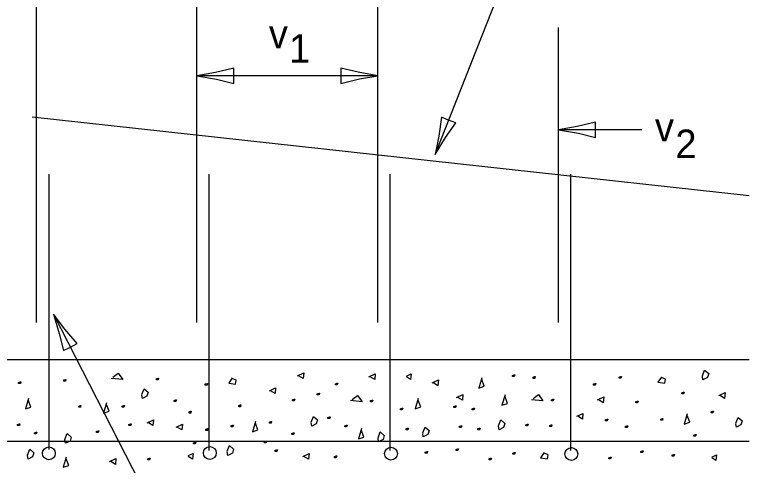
# Model space of a CAD drawing. Extents: x 2133490 to 2172050, y 2138301 to 2145980.
# Drawn here: x 2139073.9 to 2139254.8, y 2141727.2 to 2141838.2 of the extents above; entities that cross this region are included whole.
import ezdxf

# ---------------------------------------------------------------- set-up
doc = ezdxf.new("R2010")
doc.units = 0
for name, color, linetype in [('Level 40', 7, 'Continuous'), ('Level 63', 7, 'Continuous'), ('ROW_EX_Private Boundary Items', 7, 'Continuous'), ('ROW_PR_Notes', 7, 'Continuous'), ('Topo_Bridge Structures', 7, 'Continuous')]:
    doc.layers.add(name, color=color, linetype=linetype)

msp = doc.modelspace()

# ---------------------------------------------------------------- linework, layer by layer
at = {"layer": 'Level 40'}
msp.add_line((2138878.97, 2141753.19), (2139254.81, 2141753.19), dxfattribs=at)
at = {"layer": 'ROW_EX_Private Boundary Items'}
for centre in [(2139082.36, 2141730.13), (2139121.98, 2141730.21), (2139166.58, 2141730.04), (2139211.01, 2141729.95)]:
    msp.add_circle(centre, 1.58, dxfattribs=at)
at = {"layer": 'ROW_PR_Notes'}
for p, q in [((2139177.43, 2141803.74), (2139216.4, 2141902.1)), ((2139079.35, 2141762.3), (2139079.35, 2141885.77)), ((2139118.82, 2141762.3), (2139118.82, 2141865.85)), ((2139163.35, 2141762.3), (2139163.35, 2141865.85)), ((2139207.87, 2141762.3), (2139207.87, 2141835.01)), ((2139163.35, 2141823.12), (2139118.82, 2141823.12)), ((2139254.81, 2141793.52), (2139078.24, 2141812.95)), ((2139228.35, 2141809.82), (2139207.87, 2141809.82)), ((2139082.39, 2141731.04), (2139082.39, 2141798.85)), ((2139121.85, 2141730.81), (2139121.85, 2141798.85)), ((2139166.38, 2141730.81), (2139166.38, 2141798.85)), ((2139210.91, 2141730.81), (2139210.91, 2141798.85)), ((2139083.51, 2141764.38), (2139119.78, 2141693.56)), ((2138855.7, 2141733.07), (2139254.81, 2141733.07))]:
    msp.add_line(p, q, dxfattribs=at)
for points in [[(2139243.26, 2141749.22), (2139243.82, 2141750.63), (2139244.81, 2141749.79), (2139244.53, 2141748.8), (2139243.4, 2141748.24), (2139243.26, 2141749.08)], [(2139098.14, 2141748.85), (2139099.41, 2141749.83), (2139100.53, 2141748.28), (2139097.72, 2141748.57)], [(2139143.57, 2141749.24), (2139145.12, 2141749.95), (2139144.98, 2141748.54), (2139143.85, 2141749.24)], [(2139161.17, 2141748.97), (2139162.72, 2141749.67), (2139162.58, 2141748.27), (2139161.45, 2141748.97)], [(2139170.37, 2141749.16), (2139171.56, 2141749.7), (2139171.42, 2141748.29), (2139170.37, 2141748.94)], [(2139196.68, 2141749.31), (2139196.96, 2141749.45), (2139196.96, 2141749.03), (2139196.82, 2141749.03), (2139196.54, 2141749.03), (2139196.54, 2141749.03), (2139196.54, 2141749.31), (2139196.96, 2141749.45), (2139197.1, 2141749.45), (2139196.96, 2141749.03), (2139196.82, 2141749.03), (2139196.82, 2141749.45)], [(2139201.7, 2141748.85), (2139201.98, 2141749), (2139201.98, 2141748.57), (2139201.84, 2141748.57), (2139201.56, 2141748.57), (2139201.56, 2141748.57), (2139201.56, 2141748.85), (2139201.98, 2141749), (2139202.13, 2141749), (2139201.98, 2141748.57), (2139201.84, 2141748.57), (2139201.84, 2141749)], [(2139222.9, 2141748.91), (2139223.18, 2141749.05), (2139223.18, 2141748.63), (2139223.04, 2141748.63), (2139222.76, 2141748.63), (2139222.76, 2141748.63), (2139222.76, 2141748.91), (2139223.18, 2141749.05), (2139223.32, 2141749.05), (2139223.18, 2141748.63), (2139223.04, 2141748.63), (2139223.04, 2141749.05)], [(2139233.17, 2141748.91), (2139232.32, 2141747.65), (2139234.01, 2141747.37), (2139234.15, 2141748.35), (2139233.17, 2141748.77)], [(2139075.06, 2141747.58), (2139075.34, 2141747.71), (2139075.34, 2141747.29), (2139075.2, 2141747.29), (2139074.92, 2141747.29), (2139074.92, 2141747.29), (2139074.92, 2141747.58), (2139075.34, 2141747.71), (2139075.48, 2141747.71), (2139075.34, 2141747.29), (2139075.2, 2141747.29), (2139075.2, 2141747.71)], [(2139086.15, 2141748.19), (2139086.43, 2141748.33), (2139086.43, 2141747.91), (2139086.29, 2141747.91), (2139086.01, 2141747.91), (2139086.01, 2141747.91), (2139086.01, 2141748.19), (2139086.43, 2141748.33), (2139086.57, 2141748.33), (2139086.43, 2141747.91), (2139086.29, 2141747.91), (2139086.29, 2141748.33)], [(2139108.96, 2141748.52), (2139109.25, 2141748.66), (2139109.25, 2141748.23), (2139109.11, 2141748.23), (2139108.82, 2141748.23), (2139108.82, 2141748.23), (2139108.82, 2141748.52), (2139109.25, 2141748.66), (2139109.39, 2141748.66), (2139109.25, 2141748.23), (2139109.11, 2141748.23), (2139109.11, 2141748.66)], [(2139121.02, 2141747.21), (2139121.3, 2141747.35), (2139121.3, 2141746.93), (2139121.17, 2141746.93), (2139120.88, 2141746.93), (2139120.88, 2141746.93), (2139120.88, 2141747.21), (2139121.3, 2141747.35), (2139121.45, 2141747.35), (2139121.3, 2141746.93), (2139121.17, 2141746.93), (2139121.17, 2141747.35)], [(2139127.5, 2141748.7), (2139126.65, 2141747.43), (2139128.34, 2141747.15), (2139128.48, 2141748.14), (2139127.5, 2141748.56)], [(2139153.08, 2141747.23), (2139153.36, 2141747.37), (2139153.36, 2141746.95), (2139153.22, 2141746.95), (2139152.94, 2141746.95), (2139152.94, 2141746.95), (2139152.94, 2141747.23), (2139153.36, 2141747.37), (2139153.5, 2141747.37), (2139153.36, 2141746.95), (2139153.22, 2141746.95), (2139153.22, 2141747.37)], [(2139176.75, 2141747.48), (2139178.3, 2141748.19), (2139178.15, 2141746.78), (2139177.03, 2141747.48)], [(2139188.94, 2141748.74), (2139188.19, 2141746.2), (2139189.54, 2141746.65), (2139188.94, 2141748.29)], [(2139216.61, 2141747.2), (2139216.89, 2141747.34), (2139216.89, 2141746.91), (2139216.75, 2141746.91), (2139216.47, 2141746.91), (2139216.47, 2141746.91), (2139216.47, 2141747.2), (2139216.89, 2141747.34), (2139217.03, 2141747.34), (2139216.89, 2141746.91), (2139216.75, 2141746.91), (2139216.75, 2141747.34)], [(2139105.23, 2141744.62), (2139105.79, 2141746.03), (2139106.78, 2141745.18), (2139106.5, 2141744.2), (2139105.37, 2141743.64), (2139105.23, 2141744.48)], [(2139136.65, 2141745.53), (2139138.19, 2141746.24), (2139138.05, 2141744.83), (2139136.93, 2141745.53)], [(2139238.34, 2141745.02), (2139238.62, 2141745.16), (2139238.62, 2141744.74), (2139238.48, 2141744.74), (2139238.2, 2141744.74), (2139238.2, 2141744.74), (2139238.2, 2141745.02), (2139238.62, 2141745.16), (2139238.76, 2141745.16), (2139238.62, 2141744.74), (2139238.48, 2141744.74), (2139238.48, 2141745.16)], [(2139077.35, 2141743.6), (2139076.6, 2141741.07), (2139077.94, 2141741.51), (2139077.35, 2141743.16)], [(2139142.46, 2141743.31), (2139142.74, 2141743.46), (2139142.74, 2141743.03), (2139142.6, 2141743.03), (2139142.32, 2141743.03), (2139142.32, 2141743.03), (2139142.32, 2141743.31), (2139142.74, 2141743.46), (2139142.88, 2141743.46), (2139142.74, 2141743.03), (2139142.6, 2141743.03), (2139142.6, 2141743.46)], [(2139148.59, 2141744.8), (2139148.87, 2141744.94), (2139148.87, 2141744.52), (2139148.73, 2141744.52), (2139148.45, 2141744.52), (2139148.45, 2141744.52), (2139148.45, 2141744.8), (2139148.87, 2141744.94), (2139149.01, 2141744.94), (2139148.87, 2141744.52), (2139148.73, 2141744.52), (2139148.73, 2141744.94)], [(2139157.07, 2141743.39), (2139158.33, 2141744.38), (2139159.46, 2141742.83), (2139156.65, 2141743.11)], [(2139173.32, 2141743.65), (2139172.57, 2141741.11), (2139173.92, 2141741.56), (2139173.32, 2141743.2)], [(2139182.76, 2141743.9), (2139184.31, 2141744.6), (2139184.17, 2141743.19), (2139183.05, 2141743.9)], [(2139194.67, 2141744.49), (2139193.92, 2141741.95), (2139195.26, 2141742.4), (2139194.67, 2141744.04)], [(2139201.62, 2141743.61), (2139202.89, 2141744.6), (2139204.01, 2141743.05), (2139201.2, 2141743.33)], [(2139206.26, 2141743.33), (2139206.54, 2141743.47), (2139206.54, 2141743.05), (2139206.4, 2141743.05), (2139206.12, 2141743.05), (2139206.12, 2141743.05), (2139206.12, 2141743.33), (2139206.54, 2141743.47), (2139206.69, 2141743.47), (2139206.54, 2141743.05), (2139206.4, 2141743.05), (2139206.4, 2141743.47)], [(2139217.45, 2141743.3), (2139218.99, 2141744), (2139218.85, 2141742.59), (2139217.73, 2141743.3)], [(2139247.32, 2141744.36), (2139248.86, 2141745.07), (2139248.72, 2141743.66), (2139247.6, 2141744.36)], [(2139089.84, 2141741.73), (2139090.12, 2141741.87), (2139090.12, 2141741.45), (2139089.98, 2141741.45), (2139089.7, 2141741.45), (2139089.7, 2141741.45), (2139089.7, 2141741.73), (2139090.12, 2141741.87), (2139090.26, 2141741.87), (2139090.12, 2141741.45), (2139089.98, 2141741.45), (2139089.98, 2141741.87)], [(2139096.58, 2141742.56), (2139095.83, 2141740.03), (2139097.17, 2141740.47), (2139096.58, 2141742.11)], [(2139100.54, 2141741.73), (2139100.82, 2141741.87), (2139100.82, 2141741.45), (2139100.68, 2141741.45), (2139100.4, 2141741.45), (2139100.4, 2141741.45), (2139100.4, 2141741.73), (2139100.82, 2141741.87), (2139100.96, 2141741.87), (2139100.82, 2141741.45), (2139100.68, 2141741.45), (2139100.68, 2141741.87)], [(2139113.34, 2141743.13), (2139113.62, 2141743.27), (2139113.62, 2141742.85), (2139113.48, 2141742.85), (2139113.2, 2141742.85), (2139113.2, 2141742.85), (2139113.2, 2141743.13), (2139113.62, 2141743.27), (2139113.76, 2141743.27), (2139113.62, 2141742.85), (2139113.48, 2141742.85), (2139113.48, 2141743.27)], [(2139129.24, 2141741.88), (2139129.52, 2141742.02), (2139129.52, 2141741.6), (2139129.38, 2141741.6), (2139129.1, 2141741.6), (2139129.1, 2141741.6), (2139129.1, 2141741.88), (2139129.52, 2141742.02), (2139129.66, 2141742.02), (2139129.52, 2141741.6), (2139129.38, 2141741.6), (2139129.38, 2141742.02)], [(2139161.71, 2141743.11), (2139161.99, 2141743.25), (2139161.99, 2141742.83), (2139161.85, 2141742.83), (2139161.57, 2141742.83), (2139161.57, 2141742.83), (2139161.57, 2141743.11), (2139161.99, 2141743.25), (2139162.13, 2141743.25), (2139161.99, 2141742.83), (2139161.85, 2141742.83), (2139161.85, 2141743.25)], [(2139182.18, 2141741.66), (2139182.47, 2141741.81), (2139182.47, 2141741.38), (2139182.33, 2141741.38), (2139182.04, 2141741.38), (2139182.04, 2141741.38), (2139182.04, 2141741.66), (2139182.47, 2141741.81), (2139182.61, 2141741.81), (2139182.47, 2141741.38), (2139182.33, 2141741.38), (2139182.33, 2141741.81)], [(2139227.02, 2141742.84), (2139227.3, 2141742.98), (2139227.3, 2141742.56), (2139227.16, 2141742.56), (2139226.88, 2141742.56), (2139226.88, 2141742.56), (2139226.88, 2141742.84), (2139227.3, 2141742.98), (2139227.44, 2141742.98), (2139227.3, 2141742.56), (2139227.16, 2141742.56), (2139227.16, 2141742.98)], [(2139117, 2141740.32), (2139117.28, 2141740.46), (2139117.28, 2141740.04), (2139117.14, 2141740.04), (2139116.86, 2141740.04), (2139116.86, 2141740.04), (2139116.86, 2141740.32), (2139117.28, 2141740.46), (2139117.42, 2141740.46), (2139117.28, 2141740.04), (2139117.14, 2141740.04), (2139117.14, 2141740.46)], [(2139169.06, 2141741.08), (2139169.34, 2141741.22), (2139169.34, 2141740.8), (2139169.2, 2141740.8), (2139168.92, 2141740.8), (2139168.92, 2141740.8), (2139168.92, 2141741.08), (2139169.34, 2141741.22), (2139169.48, 2141741.22), (2139169.34, 2141740.8), (2139169.2, 2141740.8), (2139169.2, 2141741.22)], [(2139186.71, 2141741.08), (2139186.99, 2141741.22), (2139186.99, 2141740.8), (2139186.84, 2141740.8), (2139186.57, 2141740.8), (2139186.57, 2141740.8), (2139186.57, 2141741.08), (2139186.99, 2141741.22), (2139187.13, 2141741.22), (2139186.99, 2141740.8), (2139186.84, 2141740.8), (2139186.84, 2141741.22)], [(2139212.31, 2141739.25), (2139213.86, 2141739.95), (2139213.72, 2141738.55), (2139212.59, 2141739.25)], [(2139239.55, 2141739.87), (2139238.81, 2141737.33), (2139240.15, 2141737.78), (2139239.55, 2141739.42)], [(2139245.57, 2141740.33), (2139245.86, 2141740.47), (2139245.86, 2141740.05), (2139245.71, 2141740.05), (2139245.43, 2141740.05), (2139245.43, 2141740.05), (2139245.43, 2141740.33), (2139245.86, 2141740.47), (2139246, 2141740.47), (2139245.86, 2141740.05), (2139245.71, 2141740.05), (2139245.71, 2141740.47)], [(2139106.59, 2141737.65), (2139108.13, 2141738.35), (2139107.99, 2141736.94), (2139106.87, 2141737.65)], [(2139133.21, 2141737.96), (2139132.47, 2141735.43), (2139133.81, 2141735.87), (2139133.21, 2141737.51)], [(2139136.78, 2141737.8), (2139137.06, 2141737.94), (2139137.06, 2141737.52), (2139136.92, 2141737.52), (2139136.64, 2141737.52), (2139136.64, 2141737.52), (2139136.64, 2141737.8), (2139137.06, 2141737.94), (2139137.2, 2141737.94), (2139137.06, 2141737.52), (2139136.92, 2141737.52), (2139136.92, 2141737.94)], [(2139146.93, 2141737.77), (2139147.5, 2141739.18), (2139148.48, 2141738.34), (2139148.2, 2141737.35), (2139147.08, 2141736.79), (2139146.93, 2141737.63)], [(2139151.22, 2141738.97), (2139151.5, 2141739.11), (2139151.5, 2141738.69), (2139151.36, 2141738.69), (2139151.08, 2141738.69), (2139151.08, 2141738.69), (2139151.08, 2141738.97), (2139151.5, 2141739.11), (2139151.64, 2141739.11), (2139151.5, 2141738.69), (2139151.36, 2141738.69), (2139151.36, 2141739.11)], [(2139193.05, 2141736.92), (2139193.61, 2141738.33), (2139194.6, 2141737.48), (2139194.32, 2141736.5), (2139193.19, 2141735.94), (2139193.05, 2141736.78)], [(2139219.55, 2141738.43), (2139219.83, 2141738.57), (2139219.83, 2141738.15), (2139219.69, 2141738.15), (2139219.41, 2141738.15), (2139219.41, 2141738.15), (2139219.41, 2141738.43), (2139219.83, 2141738.57), (2139219.97, 2141738.57), (2139219.83, 2141738.15), (2139219.69, 2141738.15), (2139219.69, 2141738.57)], [(2139233.14, 2141738.55), (2139233.42, 2141738.69), (2139233.42, 2141738.26), (2139233.28, 2141738.26), (2139233, 2141738.26), (2139233, 2141738.26), (2139233, 2141738.55), (2139233.42, 2141738.69), (2139233.56, 2141738.69), (2139233.42, 2141738.26), (2139233.28, 2141738.26), (2139233.28, 2141738.69)], [(2139251.49, 2141737.56), (2139252.06, 2141738.96), (2139253.04, 2141738.12), (2139252.76, 2141737.14), (2139251.64, 2141736.57), (2139251.49, 2141737.42)], [(2139074.8, 2141737.22), (2139075.09, 2141737.36), (2139075.09, 2141736.94), (2139074.94, 2141736.94), (2139074.66, 2141736.94), (2139074.66, 2141736.94), (2139074.66, 2141737.22), (2139075.09, 2141737.36), (2139075.23, 2141737.36), (2139075.09, 2141736.94), (2139074.94, 2141736.94), (2139074.94, 2141737.36)], [(2139102.22, 2141737.22), (2139102.5, 2141737.36), (2139102.5, 2141736.94), (2139102.36, 2141736.94), (2139102.08, 2141736.94), (2139102.08, 2141736.94), (2139102.08, 2141737.22), (2139102.5, 2141737.36), (2139102.64, 2141737.36), (2139102.5, 2141736.94), (2139102.36, 2141736.94), (2139102.36, 2141737.36)], [(2139113.67, 2141736.58), (2139115.22, 2141737.29), (2139115.08, 2141735.88), (2139113.95, 2141736.58)], [(2139121.18, 2141736.05), (2139121.46, 2141736.19), (2139121.46, 2141735.77), (2139121.32, 2141735.77), (2139121.04, 2141735.77), (2139121.04, 2141735.77), (2139121.04, 2141736.05), (2139121.46, 2141736.19), (2139121.6, 2141736.19), (2139121.46, 2141735.77), (2139121.32, 2141735.77), (2139121.32, 2141736.19)], [(2139127.41, 2141736.94), (2139127.69, 2141737.08), (2139127.69, 2141736.66), (2139127.55, 2141736.66), (2139127.27, 2141736.66), (2139127.27, 2141736.66), (2139127.27, 2141736.94), (2139127.69, 2141737.08), (2139127.83, 2141737.08), (2139127.69, 2141736.66), (2139127.55, 2141736.66), (2139127.55, 2141737.08)], [(2139155.38, 2141736.92), (2139155.66, 2141737.06), (2139155.66, 2141736.64), (2139155.52, 2141736.64), (2139155.24, 2141736.64), (2139155.24, 2141736.64), (2139155.24, 2141736.92), (2139155.66, 2141737.06), (2139155.8, 2141737.06), (2139155.66, 2141736.64), (2139155.52, 2141736.64), (2139155.52, 2141737.06)], [(2139159.32, 2141736.21), (2139158.57, 2141733.67), (2139159.91, 2141734.12), (2139159.32, 2141735.76)], [(2139170.47, 2141736.2), (2139170.75, 2141736.34), (2139170.75, 2141735.92), (2139170.61, 2141735.92), (2139170.32, 2141735.92), (2139170.32, 2141735.92), (2139170.32, 2141736.2), (2139170.75, 2141736.34), (2139170.89, 2141736.34), (2139170.75, 2141735.92), (2139170.61, 2141735.92), (2139170.61, 2141736.34)], [(2139174.4, 2141735.17), (2139174.97, 2141736.58), (2139175.96, 2141735.73), (2139175.67, 2141734.75), (2139174.55, 2141734.18), (2139174.4, 2141735.03)], [(2139183.59, 2141736.78), (2139183.87, 2141736.92), (2139183.87, 2141736.5), (2139183.73, 2141736.5), (2139183.45, 2141736.5), (2139183.45, 2141736.5), (2139183.45, 2141736.78), (2139183.87, 2141736.92), (2139184.02, 2141736.92), (2139183.87, 2141736.5), (2139183.73, 2141736.5), (2139183.73, 2141736.92)], [(2139188.11, 2141736.2), (2139188.39, 2141736.34), (2139188.39, 2141735.92), (2139188.25, 2141735.92), (2139187.97, 2141735.92), (2139187.97, 2141735.92), (2139187.97, 2141736.2), (2139188.39, 2141736.34), (2139188.53, 2141736.34), (2139188.39, 2141735.92), (2139188.25, 2141735.92), (2139188.25, 2141736.34)], [(2139199.93, 2141737.14), (2139200.21, 2141737.28), (2139200.21, 2141736.86), (2139200.07, 2141736.86), (2139199.79, 2141736.86), (2139199.79, 2141736.86), (2139199.79, 2141737.14), (2139200.21, 2141737.28), (2139200.35, 2141737.28), (2139200.21, 2141736.86), (2139200.07, 2141736.86), (2139200.07, 2141737.28)], [(2139205.8, 2141736.98), (2139206.08, 2141737.12), (2139206.08, 2141736.7), (2139205.94, 2141736.7), (2139205.66, 2141736.7), (2139205.66, 2141736.7), (2139205.66, 2141736.98), (2139206.08, 2141737.12), (2139206.22, 2141737.12), (2139206.08, 2141736.7), (2139205.94, 2141736.7), (2139205.94, 2141737.12)], [(2139224.46, 2141736.78), (2139224.74, 2141736.92), (2139224.74, 2141736.5), (2139224.6, 2141736.5), (2139224.32, 2141736.5), (2139224.32, 2141736.5), (2139224.32, 2141736.78), (2139224.74, 2141736.92), (2139224.88, 2141736.92), (2139224.74, 2141736.5), (2139224.6, 2141736.5), (2139224.6, 2141736.92)], [(2139078.97, 2141735.17), (2139079.25, 2141735.31), (2139079.25, 2141734.89), (2139079.11, 2141734.89), (2139078.83, 2141734.89), (2139078.83, 2141734.89), (2139078.83, 2141735.17), (2139079.25, 2141735.31), (2139079.39, 2141735.31), (2139079.25, 2141734.89), (2139079.11, 2141734.89), (2139079.11, 2141735.31)], [(2139086.32, 2141733.56), (2139086.89, 2141734.97), (2139087.87, 2141734.13), (2139087.59, 2141733.14), (2139086.46, 2141732.58), (2139086.32, 2141733.42)], [(2139094.2, 2141735.54), (2139094.48, 2141735.68), (2139094.48, 2141735.25), (2139094.34, 2141735.25), (2139094.06, 2141735.25), (2139094.06, 2141735.25), (2139094.06, 2141735.54), (2139094.48, 2141735.68), (2139094.62, 2141735.68), (2139094.48, 2141735.25), (2139094.34, 2141735.25), (2139094.34, 2141735.68)], [(2139142.32, 2141735.03), (2139142.6, 2141735.17), (2139142.6, 2141734.75), (2139142.46, 2141734.75), (2139142.18, 2141734.75), (2139142.18, 2141734.75), (2139142.18, 2141735.03), (2139142.6, 2141735.17), (2139142.74, 2141735.17), (2139142.6, 2141734.75), (2139142.46, 2141734.75), (2139142.46, 2141735.17)], [(2139163.4, 2141733.97), (2139163.96, 2141735.37), (2139164.95, 2141734.53), (2139164.67, 2141733.54), (2139163.54, 2141732.98), (2139163.4, 2141733.82)], [(2139241.3, 2141734.6), (2139241.58, 2141734.75), (2139241.58, 2141734.32), (2139241.44, 2141734.32), (2139241.16, 2141734.32), (2139241.16, 2141734.32), (2139241.16, 2141734.6), (2139241.58, 2141734.75), (2139241.72, 2141734.75), (2139241.58, 2141734.32), (2139241.44, 2141734.32), (2139241.44, 2141734.75)], [(2139118.12, 2141732.72), (2139118.4, 2141732.86), (2139118.4, 2141732.44), (2139118.26, 2141732.44), (2139117.98, 2141732.44), (2139117.98, 2141732.44), (2139117.98, 2141732.72), (2139118.4, 2141732.86), (2139118.55, 2141732.86), (2139118.4, 2141732.44), (2139118.26, 2141732.44), (2139118.26, 2141732.86)], [(2139135.57, 2141733), (2139135.85, 2141733.14), (2139135.85, 2141732.72), (2139135.71, 2141732.72), (2139135.43, 2141732.72), (2139135.43, 2141732.72), (2139135.43, 2141733), (2139135.85, 2141733.14), (2139135.99, 2141733.14), (2139135.85, 2141732.72), (2139135.71, 2141732.72), (2139135.71, 2141733.14)], [(2139077.09, 2141729.69), (2139077.65, 2141731.1), (2139078.63, 2141730.26), (2139078.35, 2141729.27), (2139077.23, 2141728.71), (2139077.09, 2141729.55)], [(2139126.28, 2141730.61), (2139126.85, 2141732.02), (2139127.83, 2141731.17), (2139127.55, 2141730.19), (2139126.43, 2141729.62), (2139126.28, 2141730.47)], [(2139138.21, 2141730.87), (2139138.5, 2141731.01), (2139138.5, 2141730.59), (2139138.36, 2141730.59), (2139138.07, 2141730.59), (2139138.07, 2141730.59), (2139138.07, 2141730.87), (2139138.5, 2141731.01), (2139138.64, 2141731.01), (2139138.5, 2141730.59), (2139138.36, 2141730.59), (2139138.36, 2141731.01)], [(2139182.76, 2141731.09), (2139183.05, 2141731.23), (2139183.05, 2141730.8), (2139182.9, 2141730.8), (2139182.62, 2141730.8), (2139182.62, 2141730.8), (2139182.62, 2141731.09), (2139183.05, 2141731.23), (2139183.19, 2141731.23), (2139183.05, 2141730.8), (2139182.9, 2141730.8), (2139182.9, 2141731.23)], [(2139228.25, 2141730.56), (2139228.53, 2141730.7), (2139228.53, 2141730.28), (2139228.39, 2141730.28), (2139228.11, 2141730.28), (2139228.11, 2141730.28), (2139228.11, 2141730.56), (2139228.53, 2141730.7), (2139228.67, 2141730.7), (2139228.53, 2141730.28), (2139228.39, 2141730.28), (2139228.39, 2141730.7)], [(2139086.65, 2141729.21), (2139085.91, 2141726.67), (2139087.25, 2141727.12), (2139086.65, 2141728.76)], [(2139106.87, 2141728.78), (2139107.15, 2141728.92), (2139107.15, 2141728.5), (2139107.01, 2141728.5), (2139106.72, 2141728.5), (2139106.72, 2141728.5), (2139106.72, 2141728.78), (2139107.15, 2141728.92), (2139107.29, 2141728.92), (2139107.15, 2141728.5), (2139107.01, 2141728.5), (2139107.01, 2141728.92)], [(2139116.67, 2141729.56), (2139117.86, 2141730.1), (2139117.71, 2141728.7), (2139116.67, 2141729.35)], [(2139144.87, 2141729.37), (2139146.42, 2141730.07), (2139146.28, 2141728.66), (2139145.15, 2141729.37)], [(2139152.85, 2141729.32), (2139153.13, 2141729.46), (2139153.13, 2141729.04), (2139152.99, 2141729.04), (2139152.7, 2141729.04), (2139152.7, 2141729.04), (2139152.7, 2141729.32), (2139153.13, 2141729.46), (2139153.27, 2141729.46), (2139153.13, 2141729.04), (2139152.99, 2141729.04), (2139152.99, 2141729.46)], [(2139175.18, 2141730.44), (2139175.46, 2141730.59), (2139175.46, 2141730.16), (2139175.32, 2141730.16), (2139175.03, 2141730.16), (2139175.03, 2141730.16), (2139175.03, 2141730.44), (2139175.46, 2141730.59), (2139175.6, 2141730.59), (2139175.46, 2141730.16), (2139175.32, 2141730.16), (2139175.32, 2141730.59)], [(2139190.89, 2141728.82), (2139191.17, 2141728.96), (2139191.17, 2141728.54), (2139191.03, 2141728.54), (2139190.75, 2141728.54), (2139190.75, 2141728.54), (2139190.75, 2141728.82), (2139191.17, 2141728.96), (2139191.31, 2141728.96), (2139191.17, 2141728.54), (2139191.03, 2141728.54), (2139191.03, 2141728.96)], [(2139196.71, 2141730.16), (2139196.99, 2141730.31), (2139196.99, 2141729.88), (2139196.85, 2141729.88), (2139196.57, 2141729.88), (2139196.57, 2141729.88), (2139196.57, 2141730.16), (2139196.99, 2141730.31), (2139197.13, 2141730.31), (2139196.99, 2141729.88), (2139196.85, 2141729.88), (2139196.85, 2141730.31)], [(2139204.28, 2141730.31), (2139203.43, 2141729.04), (2139205.12, 2141728.76), (2139205.26, 2141729.74), (2139204.28, 2141730.16)], [(2139220.38, 2141729.03), (2139220.66, 2141729.17), (2139220.66, 2141728.74), (2139220.52, 2141728.74), (2139220.24, 2141728.74), (2139220.24, 2141728.74), (2139220.24, 2141729.03), (2139220.66, 2141729.17), (2139220.8, 2141729.17), (2139220.66, 2141728.74), (2139220.52, 2141728.74), (2139220.52, 2141729.17)], [(2139235.97, 2141729.71), (2139236.25, 2141729.85), (2139236.25, 2141729.43), (2139236.1, 2141729.43), (2139235.83, 2141729.43), (2139235.83, 2141729.43), (2139235.83, 2141729.71), (2139236.25, 2141729.85), (2139236.39, 2141729.85), (2139236.25, 2141729.43), (2139236.1, 2141729.43), (2139236.1, 2141729.85)], [(2139245.57, 2141729.19), (2139246.75, 2141729.74), (2139246.61, 2141728.33), (2139245.57, 2141728.98)], [(2139097.32, 2141728.11), (2139098.87, 2141728.81), (2139098.73, 2141727.4), (2139097.6, 2141728.11)]]:
    msp.add_lwpolyline(points, dxfattribs=at)
at = {"layer": 'Topo_Bridge Structures'}
for points in [[(2139127.92, 2141821.22), (2139127.92, 2141823.12), (2139127.92, 2141825.02), (2139123.37, 2141823.91), (2139118.82, 2141823.12), (2139123.67, 2141822.24)], [(2139154.25, 2141825.02), (2139154.24, 2141823.12), (2139154.24, 2141821.22), (2139158.8, 2141822.33), (2139163.35, 2141823.12), (2139158.49, 2141824)], [(2139182.55, 2141811.5), (2139180.78, 2141812.2), (2139179.01, 2141812.9), (2139178.37, 2141808.26), (2139177.43, 2141803.74), (2139180.04, 2141807.93)], [(2139216.97, 2141807.91), (2139216.98, 2141809.82), (2139216.98, 2141811.72), (2139212.42, 2141810.61), (2139207.87, 2141809.82), (2139212.73, 2141808.94)], [(2139085.96, 2141755.42), (2139087.66, 2141756.28), (2139089.35, 2141757.15), (2139086.28, 2141760.69), (2139083.51, 2141764.38), (2139084.93, 2141759.66)]]:
    msp.add_lwpolyline(points, close=True, dxfattribs=at)

# ---------------------------------------------------------------- texts
at = {"layer": 'Level 63'}
for s, p in [('v', (2139136.53, 2141829.9)), ('1', (2139141.48, 2141826.34)), ('v', (2139231.58, 2141806.98)), ('2', (2139236.61, 2141802.86))]:
    msp.add_text(s, height=7, dxfattribs=at).set_placement(p)

doc.saveas('drawing.dxf')
